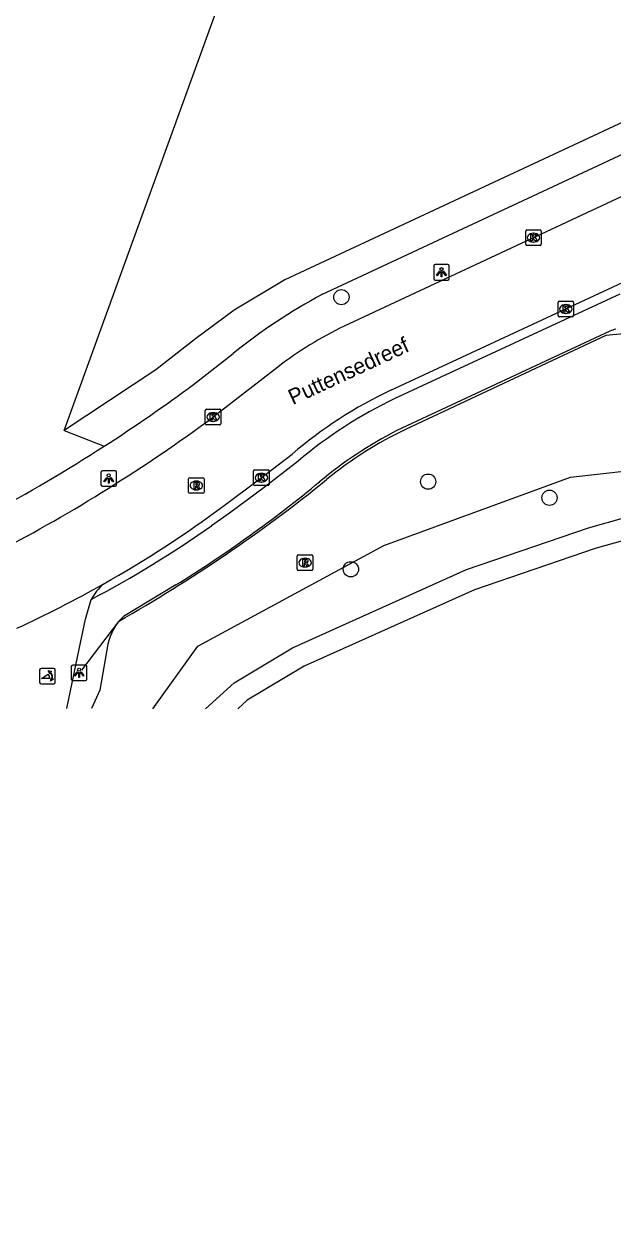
# Model space of a CAD drawing. Extents: x 163268 to 164360, y 381529 to 382285.
# Drawn here: x 163730.1 to 163767.9, y 381607.9 to 381685.3 of the extents above; entities that cross this region are included whole.
import ezdxf

# ---------------------------------------------------------------- set-up
doc = ezdxf.new("R2010")
doc.units = 0
for name, color, linetype in [('IMGEO_Boom', 7, 'Continuous'), ('IMGEO_Fietspad_open', 7, 'Continuous'), ('IMGEO_Groenvoorziening', 7, 'Continuous'), ('IMGEO_Hek', 7, 'Continuous'), ('IMGEO_Kolk', 7, 'Continuous'), ('IMGEO_Lichtpunt', 7, 'Continuous'), ('IMGEO_Openbare_ruimte_label', 7, 'Continuous'), ('IMGEO_Poller', 7, 'Continuous'), ('IMGEO_Rijbaan_lokaal_open', 7, 'Continuous'), ('IMGEO_Rioolput', 7, 'Continuous'), ('IMGEO_Voetpad_halfverhard', 7, 'Continuous'), ('IMGEO_Voetpad_open', 7, 'Continuous')]:
    doc.layers.add(name, color=color, linetype=linetype)

msp = doc.modelspace()

# ---------------------------------------------------------------- linework, layer by layer
at = {"layer": 'IMGEO_Boom'}
for centre in [(163750.455, 381667.741), (163756.023, 381655.899), (163763.805, 381654.863), (163751.063, 381650.273)]:
    msp.add_circle(centre, 0.489, dxfattribs=at)
at = {"layer": 'IMGEO_Fietspad_open'}
msp.add_lwpolyline([(163732.838, 381641.33), (163733.548, 381644.742), (163734.033, 381647.073), (163734.4, 381648.337)], dxfattribs=at)
msp.add_arc((163737.699, 381646.537), 3.759, 132.11028, 151.38088, dxfattribs=at)
at = {"layer": 'IMGEO_Groenvoorziening'}
for points in [[(163732.674, 381659.172), (163745.303, 381694.051), (163749.229, 381692.724)], [(163786.431, 381687.36), (163746.827, 381668.861), (163743.582, 381666.907), (163741.092, 381665.064), (163738.545, 381663.071), (163732.674, 381659.172)], [(163732.674, 381659.172), (163735.245, 381658.18)], [(163738.368, 381641.32), (163741.255, 381645.338), (163753.168, 381651.805), (163765.143, 381656.192), (163772.762, 381657.048), (163794.067, 381649.73), (163801.182, 381650.079), (163809.5, 381651.023), (163817.822, 381652.706), (163825.286, 381652.71), (163832.039, 381650.776), (163839.165, 381647.687), (163859.24, 381632.111), (163864.566, 381626.406), (163870.322, 381618.538), (163873.932, 381611.48), (163874.152, 381607.867)]]:
    msp.add_lwpolyline(points, dxfattribs=at)
at = {"layer": 'IMGEO_Hek'}
for points in [[(163769.024, 381665.437), (163767.416, 381665.284), (163754.604, 381659.273)], [(163736.151, 381646.931), (163733.792, 381643.791)]]:
    msp.add_lwpolyline(points, dxfattribs=at)
for centre, radius, start, end in [((163765.546, 381636.452), 25.308, 115.616, 129.33511), ((163687.497, 381732.705), 98.612, 299.56354, 308.96147)]:
    msp.add_arc(centre, radius, start, end, dxfattribs=at)
at = {"layer": 'IMGEO_Kolk'}
for p, q in [((163762.278, 381671.134), (163762.278, 381671.986)), ((163762.353, 381672.06), (163763.205, 381672.06)), ((163762.766, 381671.84), (163762.791, 381671.84)), ((163763.279, 381671.986), (163763.279, 381671.134)), ((163763.205, 381671.06), (163762.353, 381671.06)), ((163762.789, 381671.28), (163762.764, 381671.28)), ((163764.354, 381666.557), (163764.354, 381667.409)), ((163764.429, 381667.483), (163765.281, 381667.483)), ((163764.842, 381667.263), (163764.867, 381667.263)), ((163765.355, 381667.409), (163765.355, 381666.557)), ((163765.281, 381666.483), (163764.429, 381666.483)), ((163764.865, 381666.703), (163764.84, 381666.703)), ((163741.725, 381659.619), (163741.725, 381660.471)), ((163741.8, 381660.545), (163742.652, 381660.545)), ((163742.213, 381660.325), (163742.238, 381660.325)), ((163742.726, 381660.471), (163742.726, 381659.619)), ((163742.652, 381659.545), (163741.8, 381659.545)), ((163742.236, 381659.765), (163742.211, 381659.765)), ((163744.825, 381655.724), (163744.825, 381656.576)), ((163744.9, 381656.65), (163745.752, 381656.65)), ((163745.313, 381656.43), (163745.338, 381656.43)), ((163745.826, 381656.576), (163745.826, 381655.724)), ((163745.752, 381655.65), (163744.9, 381655.65)), ((163745.336, 381655.87), (163745.311, 381655.87))]:
    msp.add_line(p, q, dxfattribs=at)
for points in [[(163762.278, 381671.134), (163762.278, 381671.986)], [(163762.353, 381672.06), (163763.205, 381672.06)], [(163762.599, 381671.76), (163762.722, 381671.76), (163762.722, 381671.609), (163762.852, 381671.76), (163763.016, 381671.76), (163762.87, 381671.609), (163763.023, 381671.36), (163762.871, 381671.36), (163762.786, 381671.524), (163762.722, 381671.457), (163762.722, 381671.36), (163762.599, 381671.36), (163762.599, 381671.76)], [(163763.279, 381671.986), (163763.279, 381671.134)], [(163763.205, 381671.06), (163762.353, 381671.06)], [(163764.354, 381666.557), (163764.354, 381667.409)], [(163764.429, 381667.483), (163765.281, 381667.483)], [(163764.675, 381667.183), (163764.798, 381667.183), (163764.798, 381667.032), (163764.928, 381667.183), (163765.092, 381667.183), (163764.946, 381667.032), (163765.099, 381666.783), (163764.947, 381666.783), (163764.862, 381666.947), (163764.798, 381666.88), (163764.798, 381666.783), (163764.675, 381666.783), (163764.675, 381667.183)], [(163765.355, 381667.409), (163765.355, 381666.557)], [(163765.281, 381666.483), (163764.429, 381666.483)], [(163741.725, 381659.619), (163741.725, 381660.471)], [(163741.8, 381660.545), (163742.652, 381660.545)], [(163742.046, 381660.245), (163742.169, 381660.245), (163742.169, 381660.094), (163742.299, 381660.245), (163742.463, 381660.245), (163742.317, 381660.094), (163742.47, 381659.845), (163742.318, 381659.845), (163742.233, 381660.009), (163742.169, 381659.942), (163742.169, 381659.845), (163742.046, 381659.845), (163742.046, 381660.245)], [(163742.726, 381660.471), (163742.726, 381659.619)], [(163742.652, 381659.545), (163741.8, 381659.545)], [(163744.825, 381655.724), (163744.825, 381656.576)], [(163744.9, 381656.65), (163745.752, 381656.65)], [(163745.146, 381656.35), (163745.269, 381656.35), (163745.269, 381656.199), (163745.399, 381656.35), (163745.563, 381656.35), (163745.417, 381656.199), (163745.57, 381655.95), (163745.418, 381655.95), (163745.333, 381656.114), (163745.269, 381656.047), (163745.269, 381655.95), (163745.146, 381655.95), (163745.146, 381656.35)], [(163745.826, 381656.576), (163745.826, 381655.724)], [(163745.752, 381655.65), (163744.9, 381655.65)]]:
    msp.add_lwpolyline(points, dxfattribs=at)
for centre, start, end in [((163762.355, 381671.984), 91.55205, 178.44795), ((163762.355, 381671.984), 91.55205, 178.44795), ((163763.203, 381671.984), 1.55205, 88.44795), ((163763.203, 381671.984), 1.55205, 88.44795), ((163762.355, 381671.136), 181.55205, 268.44795), ((163762.355, 381671.136), 181.55205, 268.44795), ((163763.203, 381671.136), 271.55205, 358.44795), ((163763.203, 381671.136), 271.55205, 358.44795), ((163764.431, 381667.407), 91.55205, 178.44795), ((163764.431, 381667.407), 91.55205, 178.44795), ((163765.279, 381667.407), 1.55205, 88.44795), ((163765.279, 381667.407), 1.55205, 88.44795), ((163764.431, 381666.559), 181.55205, 268.44795), ((163764.431, 381666.559), 181.55205, 268.44795), ((163765.279, 381666.559), 271.55205, 358.44795), ((163765.279, 381666.559), 271.55205, 358.44795), ((163741.802, 381660.469), 91.55205, 178.44795), ((163741.802, 381660.469), 91.55205, 178.44795), ((163742.65, 381660.469), 1.55205, 88.44795), ((163742.65, 381660.469), 1.55205, 88.44795), ((163741.802, 381659.621), 181.55205, 268.44795), ((163741.802, 381659.621), 181.55205, 268.44795), ((163742.65, 381659.621), 271.55205, 358.44795), ((163742.65, 381659.621), 271.55205, 358.44795), ((163744.902, 381656.574), 91.55205, 178.44795), ((163744.902, 381656.574), 91.55205, 178.44795), ((163745.75, 381656.574), 1.55205, 88.44795), ((163745.75, 381656.574), 1.55205, 88.44795), ((163744.902, 381655.726), 181.55205, 268.44795), ((163744.902, 381655.726), 181.55205, 268.44795), ((163745.75, 381655.726), 271.55205, 358.44795), ((163745.75, 381655.726), 271.55205, 358.44795)]:
    msp.add_arc(centre, 0.0765, start, end, dxfattribs=at)
for centre, major_axis, ratio, start_param, end_param in [((163762.765, 381671.56), (-0.387, 0.002), 0.722429, 4.712389, 7.853982), ((163762.79, 381671.56), (-0.39, 0.002), 0.717154, 1.570796, 4.712389), ((163764.841, 381666.983), (-0.387, 0.002), 0.722429, 4.712389, 7.853982), ((163764.866, 381666.983), (-0.39, 0.002), 0.717154, 1.570796, 4.712389), ((163742.212, 381660.045), (-0.387, 0.002), 0.722429, 4.712389, 7.853982), ((163742.237, 381660.045), (-0.39, 0.002), 0.717154, 1.570796, 4.712389), ((163745.312, 381656.15), (-0.387, 0.002), 0.722429, 4.712389, 7.853982), ((163745.337, 381656.15), (-0.39, 0.002), 0.717154, 1.570796, 4.712389)]:
    msp.add_ellipse(centre, major_axis=major_axis, ratio=ratio, start_param=start_param, end_param=end_param, dxfattribs=at)
at = {"layer": 'IMGEO_Lichtpunt'}
for p, q in [((163756.38, 381669.744), (163756.38, 381668.937)), ((163756.38, 381669.744), (163756.38, 381668.937)), ((163757.282, 381669.839), (163756.474, 381669.839)), ((163757.282, 381669.839), (163756.474, 381669.839)), ((163757.376, 381668.937), (163757.376, 381669.744)), ((163757.376, 381668.937), (163757.376, 381669.744)), ((163756.474, 381668.843), (163757.282, 381668.843)), ((163756.474, 381668.843), (163757.282, 381668.843)), ((163735.03, 381656.506), (163735.03, 381655.699)), ((163735.03, 381656.506), (163735.03, 381655.699)), ((163735.932, 381656.601), (163735.124, 381656.601)), ((163735.932, 381656.601), (163735.124, 381656.601)), ((163736.026, 381655.699), (163736.026, 381656.506)), ((163736.026, 381655.699), (163736.026, 381656.506)), ((163735.124, 381655.605), (163735.932, 381655.605)), ((163735.124, 381655.605), (163735.932, 381655.605)), ((163733.129, 381644.03), (163733.129, 381643.223)), ((163733.129, 381644.03), (163733.129, 381643.223)), ((163734.031, 381644.125), (163733.223, 381644.125)), ((163734.031, 381644.125), (163733.223, 381644.125)), ((163734.125, 381643.223), (163734.125, 381644.03)), ((163734.125, 381643.223), (163734.125, 381644.03)), ((163733.223, 381643.129), (163734.031, 381643.129)), ((163733.223, 381643.129), (163734.031, 381643.129))]:
    msp.add_line(p, q, dxfattribs=at)
for points in [[(163756.754, 381669.408), (163756.793, 381669.38), (163756.605, 381669.118), (163756.567, 381669.145), (163756.754, 381669.408)], [(163756.966, 381669.38), (163757.004, 381669.407), (163757.191, 381669.145), (163757.152, 381669.117), (163756.966, 381669.38)], [(163756.856, 381669.36), (163756.903, 381669.36), (163756.903, 381669.038), (163756.856, 381669.038), (163756.856, 381669.36)], [(163735.404, 381656.17), (163735.443, 381656.142), (163735.255, 381655.88), (163735.217, 381655.907), (163735.404, 381656.17)], [(163735.506, 381656.122), (163735.553, 381656.122), (163735.553, 381655.8), (163735.506, 381655.8), (163735.506, 381656.122)], [(163735.616, 381656.142), (163735.654, 381656.169), (163735.841, 381655.907), (163735.802, 381655.879), (163735.616, 381656.142)], [(163733.503, 381643.694), (163733.542, 381643.666), (163733.354, 381643.404), (163733.316, 381643.431), (163733.503, 381643.694)], [(163733.605, 381643.646), (163733.652, 381643.646), (163733.652, 381643.324), (163733.605, 381643.324), (163733.605, 381643.646)], [(163733.715, 381643.666), (163733.753, 381643.693), (163733.94, 381643.431), (163733.901, 381643.403), (163733.715, 381643.666)]]:
    msp.add_lwpolyline(points, dxfattribs=at)
for centre in [(163756.879, 381669.542), (163735.529, 381656.304), (163733.628, 381643.828)]:
    msp.add_circle(centre, 0.0994, dxfattribs=at)
for centre, start, end in [((163756.474, 381669.744), 90, 180), ((163756.474, 381669.744), 90, 180), ((163757.282, 381669.744), 0, 90), ((163757.282, 381669.744), 0, 90), ((163756.474, 381668.937), 180, 270), ((163756.474, 381668.937), 180, 270), ((163757.282, 381668.937), 270, 0), ((163757.282, 381668.937), 270, 360), ((163735.124, 381656.506), 90, 180), ((163735.124, 381656.506), 90, 180), ((163735.932, 381656.506), 0, 90), ((163735.932, 381656.506), 0, 90), ((163735.124, 381655.699), 180, 270), ((163735.124, 381655.699), 180, 270), ((163735.932, 381655.699), 270, 0), ((163735.932, 381655.699), 270, 360), ((163733.223, 381644.03), 90, 180), ((163733.223, 381644.03), 90, 180), ((163734.031, 381644.03), 0, 90), ((163734.031, 381644.03), 0, 90), ((163733.223, 381643.223), 180, 270), ((163733.223, 381643.223), 180, 270), ((163734.031, 381643.223), 270, 0), ((163734.031, 381643.223), 270, 360)]:
    msp.add_arc(centre, 0.0946, start, end, dxfattribs=at)
at = {"layer": 'IMGEO_Poller'}
for p, q in [((163731.996, 381643.908), (163731.188, 381643.908)), ((163731.996, 381643.908), (163731.188, 381643.908)), ((163731.094, 381643.813), (163731.094, 381643.006)), ((163731.094, 381643.813), (163731.094, 381643.006)), ((163732.09, 381643.006), (163732.09, 381643.813)), ((163732.09, 381643.006), (163732.09, 381643.813)), ((163731.188, 381642.911), (163731.996, 381642.911)), ((163731.188, 381642.911), (163731.996, 381642.911))]:
    msp.add_line(p, q, dxfattribs=at)
for points in [[(163731.729, 381643.264), (163731.216, 381643.264), (163731.646, 381643.539)], [(163731.773, 381643.637), (163731.761, 381643.564), (163731.636, 381643.769)], [(163731.636, 381643.769), (163731.867, 381643.703), (163731.796, 381643.671)], [(163731.789, 381643.092), (163731.855, 381643.323), (163731.885, 381643.255)], [(163731.921, 381643.228), (163731.993, 381643.217), (163731.789, 381643.092)]]:
    msp.add_lwpolyline(points, dxfattribs=at)
for centre, radius, start, end in [((163731.188, 381643.813), 0.0946, 90, 180), ((163731.188, 381643.813), 0.0946, 90, 180), ((163731.996, 381643.813), 0.0946, 0, 90), ((163731.996, 381643.813), 0.0946, 0, 90), ((163731.401, 381643.314), 0.332, 351.32473, 42.4854), ((163731.415, 381643.324), 0.476, 351.75274, 41.16905), ((163731.415, 381643.324), 0.516, 349.35686, 42.29123), ((163731.188, 381643.006), 0.0946, 180, 270), ((163731.188, 381643.006), 0.0946, 180, 270), ((163731.996, 381643.006), 0.0946, 270, 0), ((163731.996, 381643.006), 0.0946, 270, 0)]:
    msp.add_arc(centre, radius, start, end, dxfattribs=at)
at = {"layer": 'IMGEO_Rijbaan_lokaal_open'}
for points in [[(163786.999, 381682.891), (163783.052, 381681.039), (163750.632, 381665.886)], [(163753.627, 381661.773), (163789.138, 381678.296)], [(163746.372, 381663.245), (163742.224, 381660.042)], [(163742.931, 381654.361), (163745.139, 381656.008), (163747.292, 381657.671)]]:
    msp.add_lwpolyline(points, dxfattribs=at)
for centre, radius, start, end in [((163761.087, 381644.266), 24.015, 115.80687, 127.78707), ((163766.068, 381635.616), 28.965, 115.43791, 130.40932), ((163679.991, 381744.224), 104.688, 297.5623, 306.4746), ((163698.435, 381714.37), 74.706, 299.46214, 306.5565), ((163698.206, 381714.612), 75.029, 294.76703, 299.52352)]:
    msp.add_arc(centre, radius, start, end, dxfattribs=at)
at = {"layer": 'IMGEO_Rioolput'}
for p, q in [((163740.649, 381655.226), (163740.649, 381656.078)), ((163740.724, 381656.152), (163741.576, 381656.152)), ((163741.137, 381655.932), (163741.162, 381655.932)), ((163741.65, 381656.078), (163741.65, 381655.226)), ((163741.576, 381655.152), (163740.724, 381655.152)), ((163741.16, 381655.372), (163741.135, 381655.372)), ((163747.626, 381650.274), (163747.626, 381651.126)), ((163747.701, 381651.2), (163748.553, 381651.2)), ((163748.114, 381650.98), (163748.139, 381650.98)), ((163748.627, 381651.126), (163748.627, 381650.274)), ((163748.553, 381650.2), (163747.701, 381650.2)), ((163748.137, 381650.42), (163748.112, 381650.42))]:
    msp.add_line(p, q, dxfattribs=at)
for points in [[(163740.649, 381655.226), (163740.649, 381656.078)], [(163740.724, 381656.152), (163741.576, 381656.152)], [(163741.238, 381655.85), (163740.986, 381655.852), (163740.986, 381655.452)], [(163740.986, 381655.452), (163741.11, 381655.452), (163741.11, 381655.614), (163741.121, 381655.614)], [(163741.164, 381655.771), (163741.11, 381655.771), (163741.11, 381655.69)], [(163741.11, 381655.69), (163741.162, 381655.69)], [(163741.168, 381655.585), (163741.239, 381655.452), (163741.379, 381655.452), (163741.314, 381655.578)], [(163741.65, 381656.078), (163741.65, 381655.226)], [(163741.576, 381655.152), (163740.724, 381655.152)], [(163747.626, 381650.274), (163747.626, 381651.126)], [(163747.701, 381651.2), (163748.553, 381651.2)], [(163748.215, 381650.898), (163747.963, 381650.9), (163747.963, 381650.5)], [(163748.141, 381650.819), (163748.087, 381650.819), (163748.087, 381650.738)], [(163748.627, 381651.126), (163748.627, 381650.274)], [(163748.553, 381650.2), (163747.701, 381650.2)], [(163747.963, 381650.5), (163748.087, 381650.5), (163748.087, 381650.662), (163748.098, 381650.662)], [(163748.087, 381650.738), (163748.139, 381650.738)], [(163748.145, 381650.633), (163748.216, 381650.5), (163748.356, 381650.5), (163748.291, 381650.626)]]:
    msp.add_lwpolyline(points, dxfattribs=at)
for centre, radius, start, end in [((163740.726, 381656.076), 0.0765, 91.55205, 178.44795), ((163740.726, 381656.076), 0.0765, 91.55205, 178.44795), ((163741.12, 381655.561), 0.0533, 26.02933, 88.69889), ((163741.146, 381655.879), 0.19, 274.7715, 282.96867), ((163741.17, 381655.675), 0.0964, 77.00612, 93.18647), ((163741.184, 381655.732), 0.0378, 276.66336, 79.67722), ((163741.237, 381655.74), 0.109, 350.36119, 89.41601), ((163741.235, 381655.74), 0.112, 277.58423, 350.98172), ((163741.219, 381655.525), 0.108, 29.51342, 73.79051), ((163741.574, 381656.076), 0.0765, 1.55205, 88.44795), ((163741.574, 381656.076), 0.0765, 1.55205, 88.44795), ((163740.726, 381655.228), 0.0765, 181.55205, 268.44795), ((163740.726, 381655.228), 0.0765, 181.55205, 268.44795), ((163741.574, 381655.228), 0.0765, 271.55205, 358.44795), ((163741.574, 381655.228), 0.0765, 271.55205, 358.44795), ((163747.703, 381651.124), 0.0765, 91.55205, 178.44795), ((163747.703, 381651.124), 0.0765, 91.55205, 178.44795), ((163748.147, 381650.723), 0.0964, 77.00612, 93.18647), ((163748.161, 381650.78), 0.0378, 276.66336, 79.67722), ((163748.214, 381650.788), 0.109, 350.36119, 89.41601), ((163748.551, 381651.124), 0.0765, 1.55205, 88.44795), ((163748.551, 381651.124), 0.0765, 1.55205, 88.44795), ((163747.703, 381650.276), 0.0765, 181.55205, 268.44795), ((163747.703, 381650.276), 0.0765, 181.55205, 268.44795), ((163748.097, 381650.609), 0.0533, 26.02933, 88.69889), ((163748.123, 381650.927), 0.19, 274.7715, 282.96867), ((163748.212, 381650.788), 0.112, 277.58423, 350.98172), ((163748.196, 381650.573), 0.108, 29.51342, 73.79051), ((163748.551, 381650.276), 0.0765, 271.55205, 358.44795), ((163748.551, 381650.276), 0.0765, 271.55205, 358.44795)]:
    msp.add_arc(centre, radius, start, end, dxfattribs=at)
for centre, major_axis, ratio, start_param, end_param in [((163741.136, 381655.652), (-0.387, 0.002), 0.722429, 4.712389, 7.853982), ((163741.161, 381655.652), (-0.39, 0.002), 0.717154, 1.570796, 4.712389), ((163748.113, 381650.7), (-0.387, 0.002), 0.722429, 4.712389, 7.853982), ((163748.138, 381650.7), (-0.39, 0.002), 0.717154, 1.570796, 4.712389)]:
    msp.add_ellipse(centre, major_axis=major_axis, ratio=ratio, start_param=start_param, end_param=end_param, dxfattribs=at)
at = {"layer": 'IMGEO_Voetpad_halfverhard'}
for points in [[(163767.687, 381665.553), (163754.015, 381659.181)], [(163739.836, 381649.268), (163736.47, 381647.246)], [(163735.47, 381645.46), (163734.949, 381642.507), (163734.423, 381641.327)]]:
    msp.add_lwpolyline(points, dxfattribs=at)
for centre, radius, start, end in [((163768.657, 381663.593), 2.187, 105.92878, 116.3329), ((163766.749, 381634.616), 27.669, 117.40197, 129.74851), ((163695.136, 381721.242), 84.725, 301.84233, 309.52521), ((163738.918, 381644.702), 3.53, 133.90347, 167.60669)]:
    msp.add_arc(centre, radius, start, end, dxfattribs=at)
at = {"layer": 'IMGEO_Voetpad_open'}
for points in [[(163749.246, 381667.928), (163785.61, 381684.914)], [(163768.314, 381667.927), (163753.881, 381661.229)], [(163740.964, 381662.138), (163743.511, 381664.131)], [(163747.672, 381657.206), (163745.502, 381655.53), (163743.287, 381653.878), (163742.111, 381653.059)], [(163741.736, 381641.313), (163743.573, 381642.994), (163747.326, 381645.239), (163758.483, 381650.251), (163766.309, 381652.941), (163771.143, 381654.297), (163775.514, 381653.611), (163780.184, 381652.14), (163787.799, 381649.105), (163791.313, 381647.923), (163794.842, 381647.503), (163798.115, 381647.496), (163801.735, 381647.703), (163805.537, 381648.258), (163814.991, 381650.302)], [(163815.251, 381648.926), (163805.772, 381646.877), (163801.876, 381646.309), (163798.153, 381646.096), (163794.757, 381646.103), (163791.004, 381646.55), (163787.316, 381647.79), (163779.714, 381650.82), (163775.193, 381652.244), (163771.227, 381652.867), (163766.726, 381651.604), (163758.997, 381648.947), (163748.07, 381644.053), (163744.412, 381641.864), (163743.806, 381641.309)]]:
    msp.add_lwpolyline(points, dxfattribs=at)
for centre, radius, start, end in [((163766.266, 381635.991), 36.189, 118.0545, 128.9606), ((163677.903, 381747.146), 105.845, 302.80351, 306.56908), ((163766.066, 381635.62), 28.36, 115.44562, 130.43524), ((163678.641, 381746.031), 104.508, 298.05329, 302.79447), ((163701.663, 381710.453), 70.215, 297.79044, 305.17382)]:
    msp.add_arc(centre, radius, start, end, dxfattribs=at)

# ---------------------------------------------------------------- texts
at = {"layer": 'IMGEO_Openbare_ruimte_label'}
msp.add_text('Puttensedreef', height=1, rotation=24.82314, dxfattribs=at).set_placement((163747.337, 381660.805))

doc.saveas('drawing.dxf')
